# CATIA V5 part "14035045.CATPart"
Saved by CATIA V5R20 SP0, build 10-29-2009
Part number: 14035045
Definition: NONE
Nomenclature: 14035045
Source: Unknown
Description: 14035045
Bounding box of the stored display mesh (mm): x -22.5 to 90, y -31.5 to 21.6, z -21.6 to 21.6
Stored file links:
  C:\Users\Utente\Desktop\IO LAVORO\3D X SITO CF\X SITO\PLASTICA\RF2\14035045.CATPart
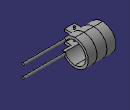
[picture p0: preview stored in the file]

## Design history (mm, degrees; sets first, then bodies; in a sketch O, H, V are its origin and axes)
Body1 "14035045" (main body)
  Solid1: solid without history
